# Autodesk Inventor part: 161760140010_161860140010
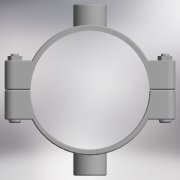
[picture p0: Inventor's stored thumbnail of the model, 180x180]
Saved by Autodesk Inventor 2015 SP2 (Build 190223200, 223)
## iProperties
Created: 2017-05
Part Number: 161760140010_161860140010
Material: Generic
Description: PLASSON DOUBLE SADDLE 140-1"
Document SubType Name: Modeling
Designer: KIM
Density: 1 g/cm^3
Appearance: Default
Author: KIM
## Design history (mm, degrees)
derived "16176.ipt"
feature "Solid1::16176.ipt"
feature "Solid2::16176.ipt"
tag "TaggingFeature1"
body "Solid1"
body "Solid2"
other parameters: "d0" = 154, "d1" = 201, "d4" = 136, "d5" = 0, "d6" = 10.05, "d7" = 201, "d8" = 0.1, "d10" = 0, "d11" = 1.4, "d20" = 1.4, "d23" = 1.4, "d36" = 15, "d37" = 12, "d38" = 78, "d39" = 0, "d40" = 3, "d41" = 5, "d42" = 0, "d44" = 3, "d45" = 0, "d46" = 1.4, "d52" = 30.291, "d53" = 21, "d54" = 0, "d55" = 25, "d57" = 0, "d58" = 151.2, "d60" = 0, "d62" = 15, "d63" = 12, "d66" = 112, "d67" = 202, "d68" = 39.3783, "d69" = 30.291, "d70" = 21, "d71" = 0, "d72" = 25, "d74" = 0, "d75" = 1.4, "B_" = 25, "G_" = 30.291, "A_" = 101, "L_" = 201, "L_1" = 136, "l_2" = 21
